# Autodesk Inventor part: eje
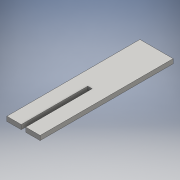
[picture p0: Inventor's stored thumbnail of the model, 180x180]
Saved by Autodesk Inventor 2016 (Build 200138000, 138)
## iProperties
Created: 2016-06
Part Number: eje
Material: Genérico
Document SubType Name: Modeling
Designer: adm
Density: 1 g/cm^3
Appearance: Valor por defecto
Author: adm
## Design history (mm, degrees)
sketch "Boceto1"
  geometry: L1 (-15, -60)-(15, -60); L2 (15, -60)-(15, 60); L3 (15, 60)-(-15, 60); L4 (-15, 60)-(-15, -60); L5 (-15, -60)-(15, 60); L6 (15, -60)-(-15, 60); L7 (-2, -60)-(-2, 0); L8 (-2, 0)-(2, 0); L9 (2, 0)-(2, -60); 1 further point
  constraints: 18 end point, 3 perpendicular, 2 midpoint, 2 parallel, 2 point on line, 1 horizontal, 1 vertical
  dimensions: "d0" = 30 distance of L3.end L2.end; "d1" = 120 distance of L2.end L1.end; "d2" = 13 distance between parallel lines of L7 L4; "d3" = 13 distance between parallel lines of L2 L9
extrude "Extrusión1" new body sketch "Boceto1" distance "d4" = 4; taper "d5" = 0 deg
node "Sólido1"
